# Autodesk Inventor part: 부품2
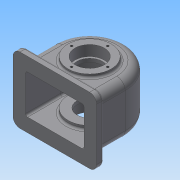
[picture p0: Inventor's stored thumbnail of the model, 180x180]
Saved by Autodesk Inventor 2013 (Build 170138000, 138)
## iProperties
Created: 2018-07
Part Number: 부품2
Material: 일반
Document SubType Name: Modeling
Designer: 05-01
Density: 1 g/cm^3
Author: 05-01
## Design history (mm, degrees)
sketch "스케치1"
  geometry: L1 (-51, 0)-(-51, -50); L2 (-51, -50)-(51, -50); L3 (51, -50)-(51, 0); A1 r 51 centre (0, 0) between (51, 0) and (-51, 0); 1 further point
  constraints: 6 end point, 2 point on circle, 2 tangent, 2 vertical, 1 centre point, 1 coincident, 1 perpendicular
  dimensions: "d1" = 50 distance from line of point (0, 0) L2; "d2" = 51 radius of A1
extrude "돌출1" new body sketch "스케치1" stored distance "d3" = 74; taper "d4" = 0 deg
fillet "모깎기2" dims "d27" = 12
feature "쉘2" dims "d30" = 9
sketch "스케치2"
  geometry: L1 (-60, -40)-(60, -40); L2 (60, -40)-(60, -50); L3 (60, -50)-(-60, -50); L4 (-60, -50)-(-60, -40); L5 (51, -50)-(-51, -50) reference; 1 further point
  constraints: 8 end point, 2 parallel, 1 collinear, 1 horizontal, 1 perpendicular
  dimensions: "d5" = 120 distance of L2.end L3.end; "d7" = 10 distance of L1.end L2.end; "d8" = 60 distance from line of point (0, 0) L4
extrude "돌출4" join sketch "스케치2" stored distance "d31" = 95; taper "d32" = 0 deg
fillet "모깎기4" dims "d33" = 10
sketch "스케치5"
  geometry: L1 (0, 0)-(100, 0) reference; L2 (-10, -10)-(-10, -85) reference; L3 (8, -19.5)-(92, -19.5); L4 (92, -19.5)-(92, -75.5); L5 (92, -75.5)-(8, -75.5); L6 (8, -75.5)-(8, -19.5); 1 further point
  constraints: 8 end point, 2 parallel, 1 horizontal, 1 perpendicular
  dimensions: "d34" = 56 distance of L5.end L3.start; "d36" = 84 distance of L3.start L3.end; "d37" = 19.5 distance between parallel lines of L1 L3; "d38" = 18 distance between parallel lines of L2 L6
extrude "돌출5" cut sketch "스케치5" distance "d39" = 10; taper "d40" = 0 deg
fillet "모깎기5" dims "d41" = 3
fillet "모깎기6" dims "d42" = 3
sketch "스케치6"
  geometry: C1 r 31 at (0, 0); A1 r 39 centre (0, 0) between (39, 0) and (-39, 0) reference
  constraints: 1 centre point, 1 coincident
  dimensions: "d43" = 62 diameter of C1
extrude "돌출6" join sketch "스케치6" distance "d44" = 5; taper "d46" = 0 deg; dims "d45" = 15, "d47" = 0
sketch "스케치7"
  geometry: C1 r 31 at (0, 0) reference; C2 r 21 at (0, 0)
  constraints: 1 centre point, 1 coincident
  dimensions: "d48" = 42 diameter of C2
extrude "돌출7" cut sketch "스케치7" distance "d49" = 15; taper "d50" = 0 deg
sketch "스케치8"
  geometry: C1 r 31 at (0, 0) reference; C2 r 18 at (0, 0)
  constraints: 1 centre point, 1 coincident
  dimensions: "d51" = 36 diameter of C2
extrude "돌출8" cut sketch "스케치8" distance "d52" = 5; taper "d53" = 0 deg
fillet "모깎기7" dims "d54" = 3
sketch "스케치9"
  geometry: C1 r 21 at (0, 0) reference; 1 further point
  constraints: 1 vertical alignment
  dimensions: "d55" = 26 distance of C1.centre point (0, 26)
hole "구멍1" sketch "스케치9" at (0, 26) diameter "d56" = 3.242; stored, may be unused: countersink angle "d60" = 90 deg, drill point angle "d62" = 118 deg; dims "d57" = 6, "d58" = 4, "d59" = 2, "d61" = 8
fillet "모깎기8" dims "d66" = 3
node "솔리드1"
pattern_circular "원형 패턴1" dims angle "d64" = 360 deg
mirror "대칭2"
other parameters: "d0" = 102, "d24" = 19
